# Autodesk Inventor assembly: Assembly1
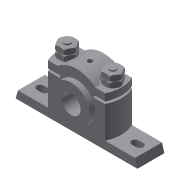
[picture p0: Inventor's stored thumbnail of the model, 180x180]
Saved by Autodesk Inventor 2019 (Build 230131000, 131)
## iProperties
Created: 2016-03
Part Number: Assembly1
Document SubType Name: Assembly
Designer: Sandeep
Author: Sandeep
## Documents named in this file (7)
- E:\_Deepak\Inventor\Projects\Autodesk Inventor_2019_Project\Resources\Inventor_2018_tut\c13_Inv_2019_tut\c13_Inv_tut_2019\c13-tut01-inv\Plummer block\Assembly1.iam
- E:\_Deepak\Inventor\Projects\Autodesk Inventor_2019_Project\Resources\Inventor_2018_tut\c13_Inv_2019_tut\c13_Inv_tut_2019\c13-tut01-inv\Plummer block\Casting.ipt
- E:\_Deepak\Inventor\Projects\Autodesk Inventor_2019_Project\Resources\Inventor_2018_tut\c13_Inv_2019_tut\c13_Inv_tut_2019\c13-tut01-inv\Plummer block\Brasses.ipt
- E:\_Deepak\Inventor\Projects\Autodesk Inventor_2019_Project\Resources\Inventor_2018_tut\c13_Inv_2019_tut\c13_Inv_tut_2019\c13-tut01-inv\Plummer block\Cap.ipt
- E:\_Deepak\Inventor\Projects\Autodesk Inventor_2019_Project\Resources\Inventor_2018_tut\c13_Inv_2019_tut\c13_Inv_tut_2019\c13-tut01-inv\Plummer block\Bolt.ipt
- E:\_Deepak\Inventor\Projects\Autodesk Inventor_2019_Project\Resources\Inventor_2018_tut\c13_Inv_2019_tut\c13_Inv_tut_2019\c13-tut01-inv\Plummer block\Nut.ipt
- E:\_Deepak\Inventor\Projects\Autodesk Inventor_2019_Project\Resources\Inventor_2018_tut\c13_Inv_2019_tut\c13_Inv_tut_2019\c13-tut01-inv\Plummer block\Lock Nut.ipt
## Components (9 placed, 6 different names)
1. Casting:1 — Mate:1, Mate:2, Insert:1, Insert:2, Angle:1, Angle:2
2. Brasses:1 — Mate:1, Mate:2, Mate:3, Mate:4
3. Cap:1 — Mate:3, Mate:4, Insert:3, Insert:5
4. Bolt:1 — Insert:1, Angle:1
5. Bolt:2 — Insert:2, Angle:2
6. Nut:1 — Insert:3, Insert:4
7. Nut:2 — Insert:5, Insert:6
8. Lock Nut:1 — Insert:4
9. Lock Nut:2 — Insert:6
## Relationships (12: Insert 6, Mate 4, Angle 2)
- Mate:1: Casting:1 ↔ Brasses:1
- Mate:2: Casting:1 ↔ Brasses:1
- Mate:3: Brasses:1 ↔ Cap:1
- Mate:4: Brasses:1 ↔ Cap:1
- Insert:1: Casting:1 ↔ Bolt:1
- Insert:2: Casting:1 ↔ Bolt:2
- Angle:1: Casting:1 ↔ Bolt:1
- Angle:2: Casting:1 ↔ Bolt:2
- Insert:3: Cap:1 ↔ Nut:1
- Insert:4: Nut:1 ↔ Lock Nut:1
- Insert:5: Cap:1 ↔ Nut:2
- Insert:6: Nut:2 ↔ Lock Nut:2
